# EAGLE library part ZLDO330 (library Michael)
3.3 VOLT ULTRA LOW DROPOUT REGULATOR
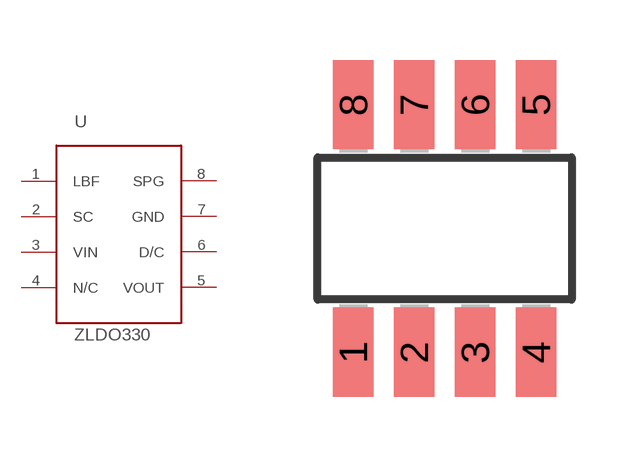
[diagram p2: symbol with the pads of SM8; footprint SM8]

Designator prefix -

## ZLDO330  [SM8]
1  LBF  out
2  SC  in
3  VIN  pwr
4  N/C  nc
5  VOUT  pwr
6  D/C  nc
7  GND  pwr
8  SPG

## Footprint SM8 (pad centres in mm)
SM8 Package
smd 1.016 x 2.235: 1 -2.286,-3.099; 2 -0.762,-3.099; 3 0.762,-3.099; 4 2.286,-3.099; 5 2.286,3.099; 6 0.762,3.099; 7 -0.762,3.099; 8 -2.286,3.099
